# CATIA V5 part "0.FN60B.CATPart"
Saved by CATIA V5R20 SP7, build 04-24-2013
Part number: 0.FN60B
Material "Nessuno"
Bounding box of the stored display mesh (mm): x 0 to 150.807, y -124.685 to 0, z -91.151 to 75.737
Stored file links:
  C:\Users\designer2\Desktop\Ottobre 2022\25-10-2022\04\Yori Evo 48V\0.FN60B.CATPart
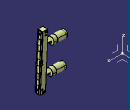
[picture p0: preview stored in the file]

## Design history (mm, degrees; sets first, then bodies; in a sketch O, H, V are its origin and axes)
AxisSystem1: origin (0, 0, 0), X (1, 0, 0), Y (0, 1, 0), Z (0, 0, 1)
Set1
  DatumSurface1
Body1 (main body), material "Nessuno"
